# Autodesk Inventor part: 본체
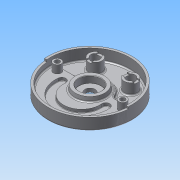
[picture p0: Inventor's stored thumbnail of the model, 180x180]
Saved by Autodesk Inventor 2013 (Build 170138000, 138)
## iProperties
Created: 2015-04
Part Number: 본체
Material: 알루미늄 6061
Document SubType Name: Modeling
Designer: Administrator
Density: 2.71 g/cm^3
Mass: 1064.1 g
Surface Area: 1033.09 cm^2
Volume: 392.655 cm^3
Author: Administrator
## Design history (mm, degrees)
sketch "스케치1"
  geometry: C1 r 95 at (0, 0); 1 further point
  constraints: 1 centre point, 1 coincident
  dimensions: "d0" = 190 diameter of C1
extrude "돌출1" new body sketch "스케치1" distance "d1" = 32; taper "d2" = 0 deg
sketch "스케치12"
  geometry: L1 (0, 0)-(-94.638, -8.28); L2 (0, 0)-(94.638, -8.28); L3 (0, 0)-(46.351, 0); A1 r 95 centre (0, 0) between (94.638, -8.28) and (-94.638, -8.28) reference
  constraints: 6 end point, 2 point on circle, 1 horizontal
  dimensions: "d64" = 5 deg angle of L2 L3; "d65" = 5 deg angle of L1 L3
extrude "돌출12" cut sketch "스케치12" distance "d66" = 5; taper "d67" = 0 deg
sketch "스케치13"
  geometry: C1 r 90 at (0, 0); A1 r 95 centre (0, 0) between (94.638, -8.28) and (-94.638, -8.28) reference
  constraints: 1 centre point, 1 coincident
  dimensions: "d68" = 180 diameter of C1
extrude "돌출13" cut sketch "스케치13" distance "d70" = 28; taper "d71" = 0 deg
sketch "스케치14"
  geometry: L1 (82.104, 12)-(47.117, 12); L2 (0, 42)-(0, 95); A1 r 95 centre (0, 0) between (91.763, 24.588) and (0, 95) reference; A2 r 10 centre (47.117, 22) between (38.056, 17.769) and (47.117, 12); A3 r 10 centre (82.104, 22) between (82.104, 12) and (91.763, 24.588); A4 r 42 centre (0, 0) between (38.056, 17.769) and (0, 42)
  constraints: 8 point on circle, 4 end point, 4 tangent, 3 centre point, 1 coincident, 1 horizontal, 1 point on line, 1 vertical
  dimensions: "d72" = 20 diameter of A2; "d73" = 20 diameter of A3; "d74" = 12 distance from line of A1.centre L1; "d75" = 84 diameter of A4
extrude "돌출14" join sketch "스케치14" distance "d76" = 7; taper "d77" = 0 deg
sketch "스케치15"
  geometry: L1 (82.104, 12)-(47.117, 12) reference; A1 r 10 centre (47.117, 22) between (38.056, 17.769) and (47.117, 12) reference; A2 r 56.174 centre (0, -19) between (46.846, 12) and (46.843, 12.004); A3 r 55.498 centre (0, -19) between (37.12, 22.257) and (20.836, 32.439); A4 r 59 centre (0, -19) between (-58.704, -13.1) and (58.704, -13.1); A5 r 41 centre (0, -19) between (-40.794, -14.9) and (40.794, -14.9); A6 r 9 centre (-49.749, -14) between (-40.794, -14.9) and (-58.704, -13.1); A7 r 9 centre (49.749, -14) between (58.704, -13.1) and (40.794, -14.9); 1 further point
  constraints: 14 point on circle, 6 centre point, 2 coincident, 2 tangent, 1 horizontal alignment, 1 point on line, 1 vertical alignment
  dimensions: "d89" = 118 diameter of A4; "d90" = 82 diameter of A5; "d91" = 18 diameter of A6; "d92" = 18 diameter of A7; "d93" = 19 distance of A2.centre point (0, 0); "d94" = 5 vertical distance of A2.centre A7.centre
extrude "돌출15" join sketch "스케치15" distance "d95" = 3; taper "d96" = 0 deg
sketch "스케치17"
  geometry: C1 r 11.5 at (0, 0); A1 r 90 centre (0, 0) between (-88.811, 14.583) and (88.811, 14.583) reference
  constraints: 1 centre point, 1 coincident
  dimensions: "d97" = 23 diameter of C1
extrude "돌출16" cut sketch "스케치17" stored distance "d98" = 14; taper "d99" = 0 deg
sketch "스케치18"
  geometry: L1 (82.104, 12)-(47.117, 12) reference; L2 (-47.117, 12)-(-82.104, 12) reference; C1 r 11.5 at (0, 0) reference; A1 r 9 centre (49.749, -14) between (58.704, -13.1) and (40.794, -14.9) reference; A2 r 59 centre (0, -19) between (-58.704, -13.1) and (58.704, -13.1) reference; A3 r 9 centre (-49.749, -14) between (-40.794, -14.9) and (-58.704, -13.1) reference; A4 r 41 centre (0, -19) between (-40.794, -14.9) and (40.794, -14.9) reference; A5 r 10 centre (82.104, 22) between (82.104, 12) and (88.811, 14.583) reference; A6 r 10 centre (47.117, 22) between (38.056, 17.769) and (47.117, 12) reference; A7 r 42 centre (0, 0) between (38.056, 17.769) and (-38.056, 17.769) reference; A8 r 10 centre (-47.117, 22) between (-47.117, 12) and (-38.056, 17.769) reference; A9 r 10 centre (-82.104, 22) between (-88.811, 14.583) and (-82.104, 12) reference; A10 r 90 centre (0, 0) between (-88.811, 14.583) and (88.811, 14.583) reference
extrude "돌출17" join sketch "스케치18" distance "d100" = 10; taper "d101" = 0 deg
sketch "스케치19"
  geometry: C1 r 35 at (0, 0); A1 r 90 centre (0, 0) between (-88.811, 14.583) and (88.811, 14.583) reference
  constraints: 1 centre point, 1 coincident
  dimensions: "d102" = 70 diameter of C1
extrude "돌출18" join sketch "스케치19" distance "d103" = 10; taper "d104" = -10 deg
sketch "스케치20"
  geometry: C1 r 33.237 at (0, 0) reference; C2 r 25 at (0, 0)
  constraints: 1 centre point, 1 coincident
  dimensions: "d105" = 50 diameter of C2
extrude "돌출19" cut sketch "스케치20" distance "d106" = 15; taper "d107" = 0 deg
sketch "스케치21"
  geometry: C1 r 15 at (-40, 52); C2 r 15 at (40, 52); A1 r 90 centre (0, 0) between (88.811, 14.583) and (-88.811, 14.583) reference
  constraints: 2 centre point, 1 horizontal alignment
  dimensions: "d108" = 30 diameter of C1; "d109" = 30 diameter of C2; "d110" = 80 distance of C1.centre C2.centre; "d111" = 40 horizontal distance of A1.centre C1.centre; "d112" = 52 vertical distance of A1.centre C2.centre
extrude "돌출20" join sketch "스케치21" distance "d113" = 25; taper "d114" = 0 deg
sketch "스케치22"
  geometry: C1 r 15 at (0, 0) reference; C2 r 10 at (0, 0); 1 further point
  constraints: 1 centre point, 1 coincident
  dimensions: "d115" = 20 diameter of C2
extrude "돌출21" cut sketch "스케치22" stored distance "d116" = 25; taper "d117" = 0 deg
sketch "스케치23"
  geometry: L1 (-6, 21.981)-(6, 21.981); L2 (6, 21.981)-(6, -18.874); L3 (6, -18.874)-(-6, -18.874); L4 (-6, -18.874)-(-6, 21.981); C1 r 10 at (0, 0) reference; 1 further point
  constraints: 8 end point, 2 parallel, 1 horizontal, 1 perpendicular
  dimensions: "d118" = 12 distance of L2.end L3.end; "d120" = 6 distance from line of L4 C1.centre
extrude "돌출22" cut sketch "스케치23" distance "d121" = 3; taper "d122" = 0 deg
sketch "스케치24"
  geometry: C1 r 11.5 at (0, 0) reference; C2 r 9 at (-74, 0)
  constraints: 1 centre point, 1 horizontal alignment
  dimensions: "d123" = 18 diameter of C2; "d124" = 74 distance of C1.centre C2.centre
extrude "돌출23" cut sketch "스케치24" distance "d125" = 11; taper "d126" = 0 deg
sketch "스케치25"
  geometry: C1 r 9 at (0, 0) reference; C2 r 5.5 at (0, 0); 1 further point
  constraints: 1 centre point, 1 coincident
  dimensions: "d127" = 11 diameter of C2
extrude "돌출24" cut sketch "스케치25" distance "d128" = 11; taper "d129" = 0 deg
sketch "스케치27"
  geometry: L1 (0, 0)-(-50.912, -50.912); L2 (0, 0)-(50.912, -50.912); L3 (0, 0)-(0, 32.916); C1 r 95 at (0, 0) reference; A1 r 51 centre (0, 0) between (-36.062, -36.062) and (36.062, -36.062); A2 r 72 centre (0, 0) between (-50.912, -50.912) and (50.912, -50.912)
  constraints: 6 end point, 4 point on circle, 2 centre point, 2 coincident, 2 point on line, 1 vertical
  dimensions: "d131" = 102 diameter of A1; "d132" = 144 diameter of A2; "d133" = 90 deg angle of L1 L2; "d134" = 45 deg angle of L3 L1
extrude "돌출25" join sketch "스케치27" distance "d135" = 5; taper "d136" = 0 deg
fillet "모깎기2" dims "d137" = 5
fillet "모깎기3" dims "d138" = 3
fillet "모깎기4" dims "d139" = 5
sketch "스케치28"
  geometry: C1 r 68 at (0, 0); 1 further point
  constraints: 1 centre point, 1 coincident, 1 other
  dimensions: "d140" = 136 diameter of C1
feature "엠보싱1" sketch "스케치28" dims "d0" = 190, "d141" = 0.5, "d142" = 0
fillet "모깎기5" dims "d143" = 3
fillet "모깎기6" dims "d144" = 1
fillet "모깎기7" dims "d145" = 0.3
chamfer "모따기1" distance "d146" = 1; stored, may be unused: second distance "d147" = 2, angle "d148" = 45 deg
fillet "모깎기8" dims "d149" = 3
chamfer "모따기2" distance "d150" = 1; stored, may be unused: second distance "d151" = 2, angle "d152" = 45 deg
sketch "스케치29"
  geometry: C1 r 5.5 at (-74, 0) reference; C2 r 5.5 at (74, 0) reference; C3 r 9 at (74, 0); C4 r 9 at (-74, 0)
  constraints: 2 centre point, 2 coincident
  dimensions: "d153" = 18 diameter of C3; "d154" = 18 diameter of C4
extrude "돌출26" join sketch "스케치29" stored distance "d155" = 5; taper "d156" = 0 deg
sketch "스케치30"
  geometry: L1 (0.789, 58)-(62.043, 58); L2 (62.043, 58)-(62.043, 46); L3 (62.043, 46)-(0.789, 46); L4 (0.789, 46)-(0.789, 58); A1 r 15 centre (40, 52) between (46, 38.252) and (46, 65.748) reference; 1 further point
  constraints: 8 end point, 2 parallel, 1 horizontal, 1 perpendicular
  dimensions: "d157" = 12 distance of L1.end L2.end; "d160" = 6 distance from line of A1.centre L1
extrude "돌출27" cut sketch "스케치30" distance "d161" = 3; taper "d162" = 0 deg
sketch "스케치31"
  geometry: L1 (-6, -13.748)-(-6, -8) reference; L2 (6, -8)-(6, -13.748) reference; A1 r 10 centre (0, 0) between (-6, -8) and (6, -8) reference; A2 r 15 centre (0, 0) between (-6, -13.748) and (6, -13.748) reference; 1 further point
extrude "돌출28" join sketch "스케치31" distance "d163" = 3; taper "d164" = 0 deg
sketch "스케치32"
  geometry: L1 (6, 13.748)-(6, 8) reference; L2 (-6, 8)-(-6, 13.748) reference; A1 r 10 centre (0, 0) between (6, 8) and (-6, 8) reference; A2 r 15 centre (0, 0) between (6, 13.748) and (-6, 13.748) reference; 1 further point
extrude "돌출29" join sketch "스케치32" distance "d165" = 3; taper "d166" = 0 deg
node "솔리드1"
mirror "대칭1"
mirror "대칭2"
mirror "대칭3"
other parameters: "d21" = 118, "d78" = 118
